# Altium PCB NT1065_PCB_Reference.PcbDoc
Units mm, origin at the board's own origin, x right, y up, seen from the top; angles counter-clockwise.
Board outline 27.75 x 27.4 mm, 4 copper layers (Top Layer, 02In, 03In, Bottom Layer), stack 1.418 mm thick; 37 components, 41 nets, 161 pads, 117 vias.
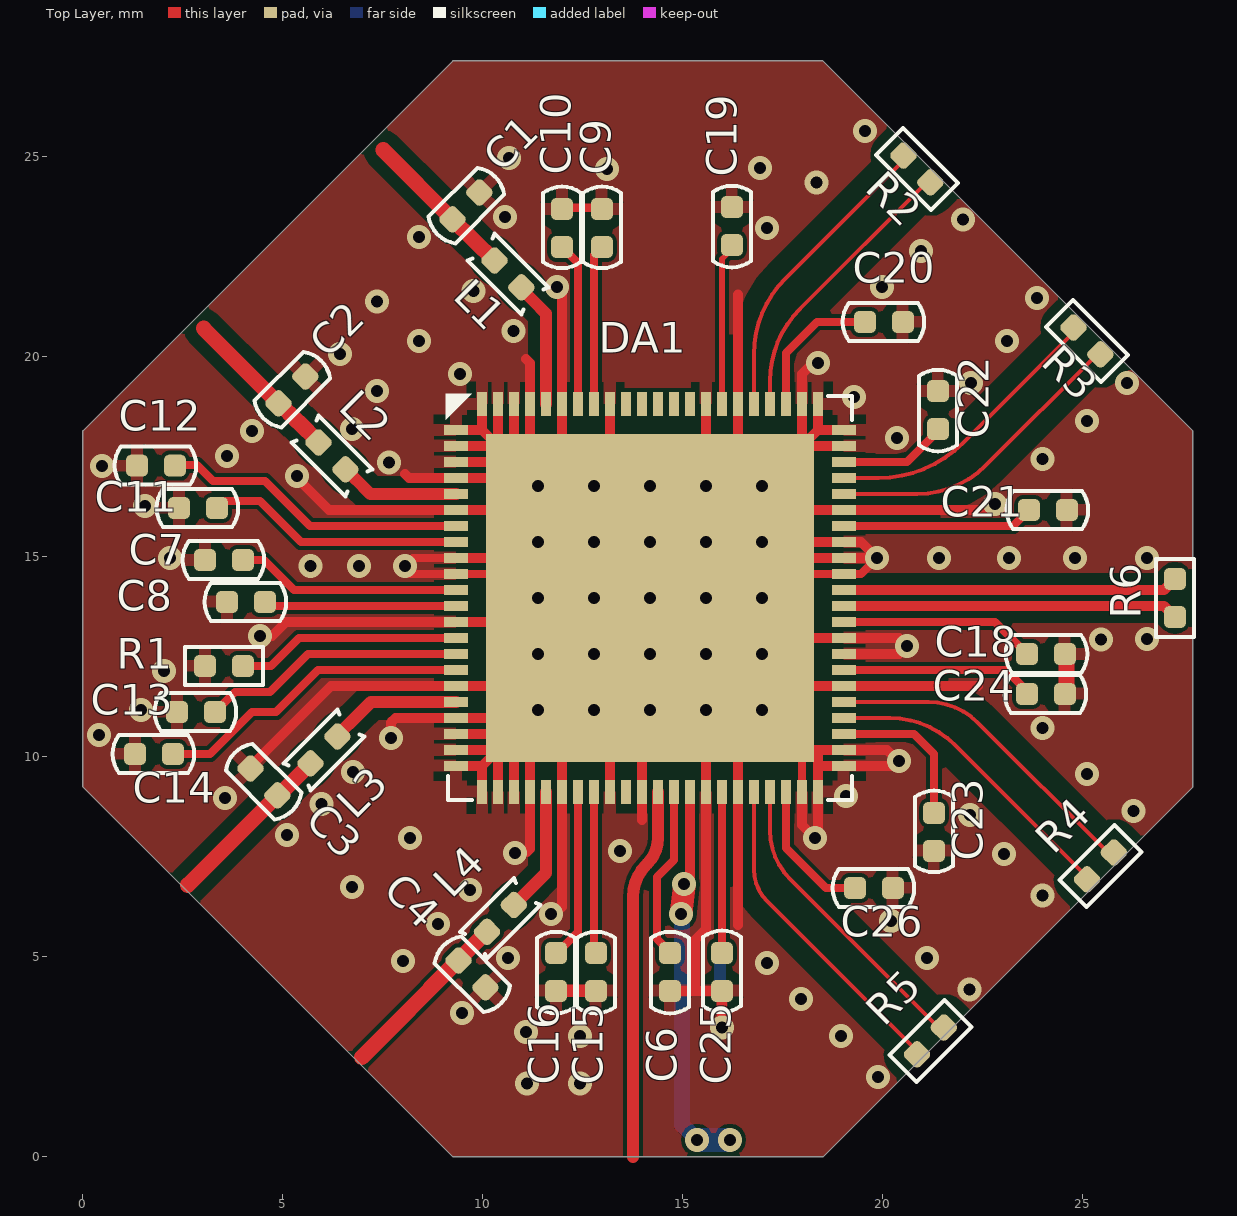
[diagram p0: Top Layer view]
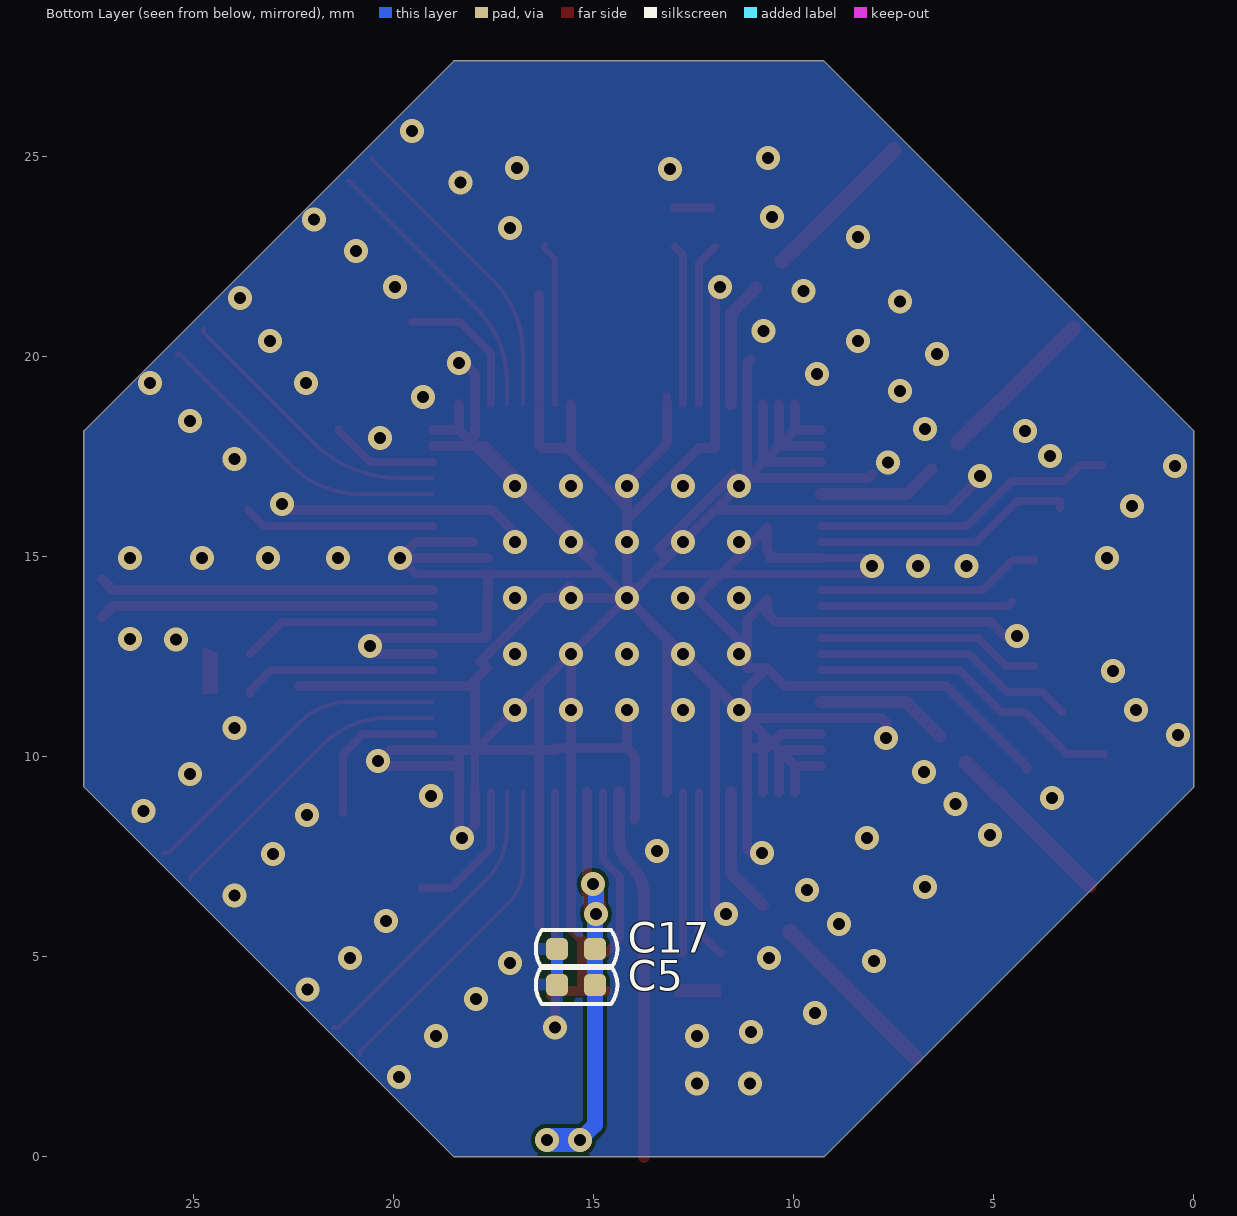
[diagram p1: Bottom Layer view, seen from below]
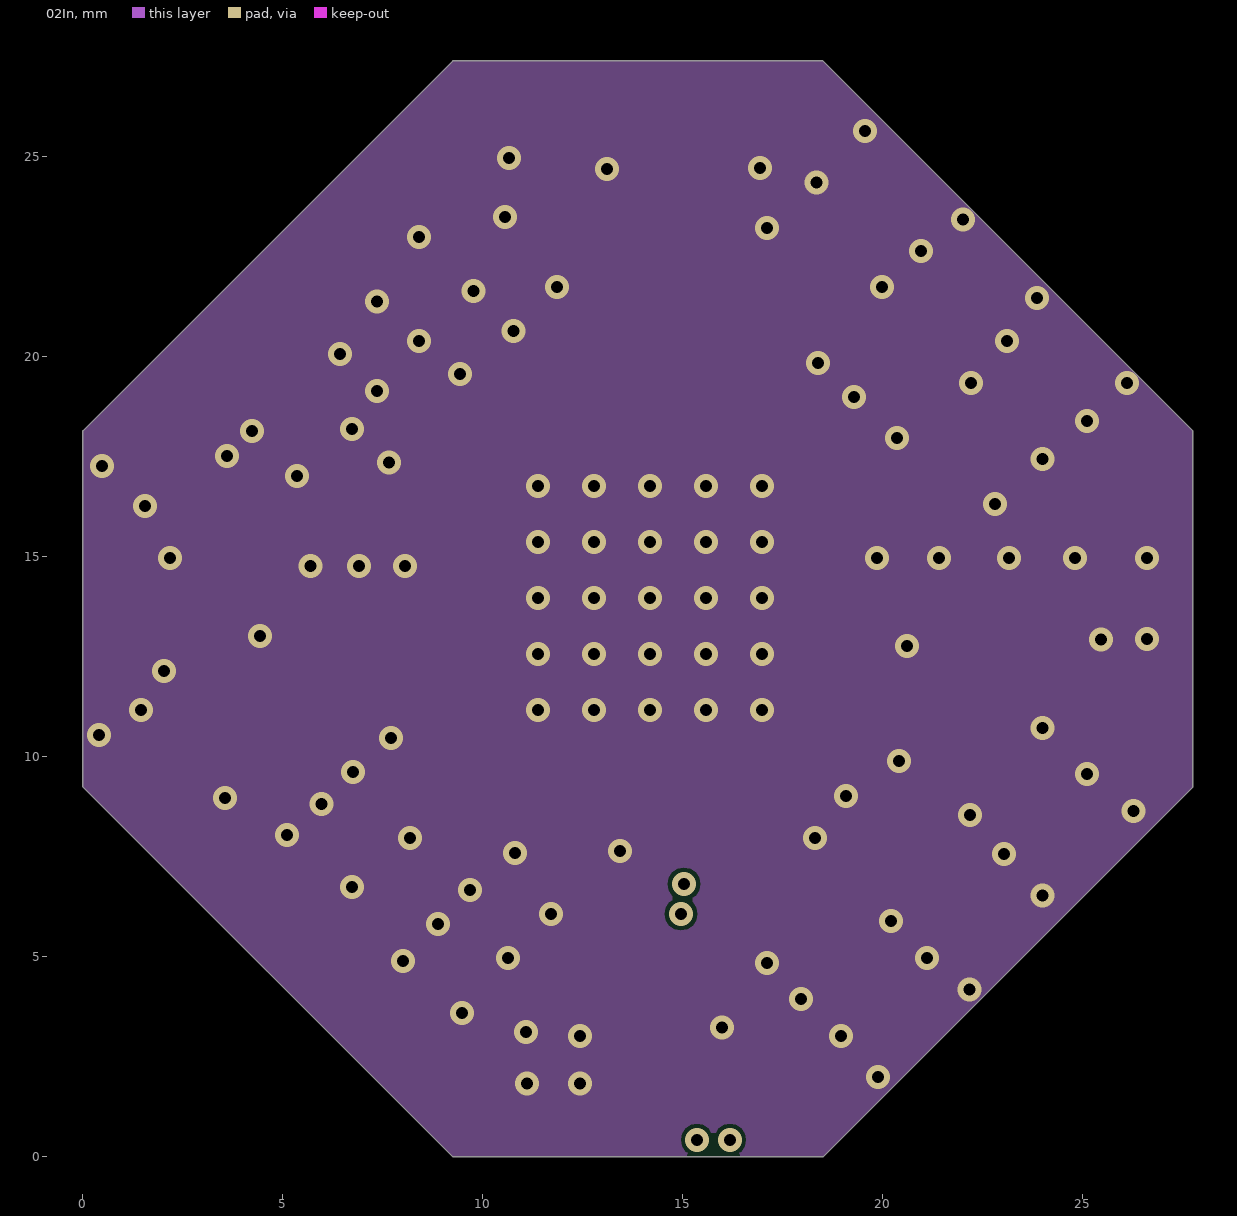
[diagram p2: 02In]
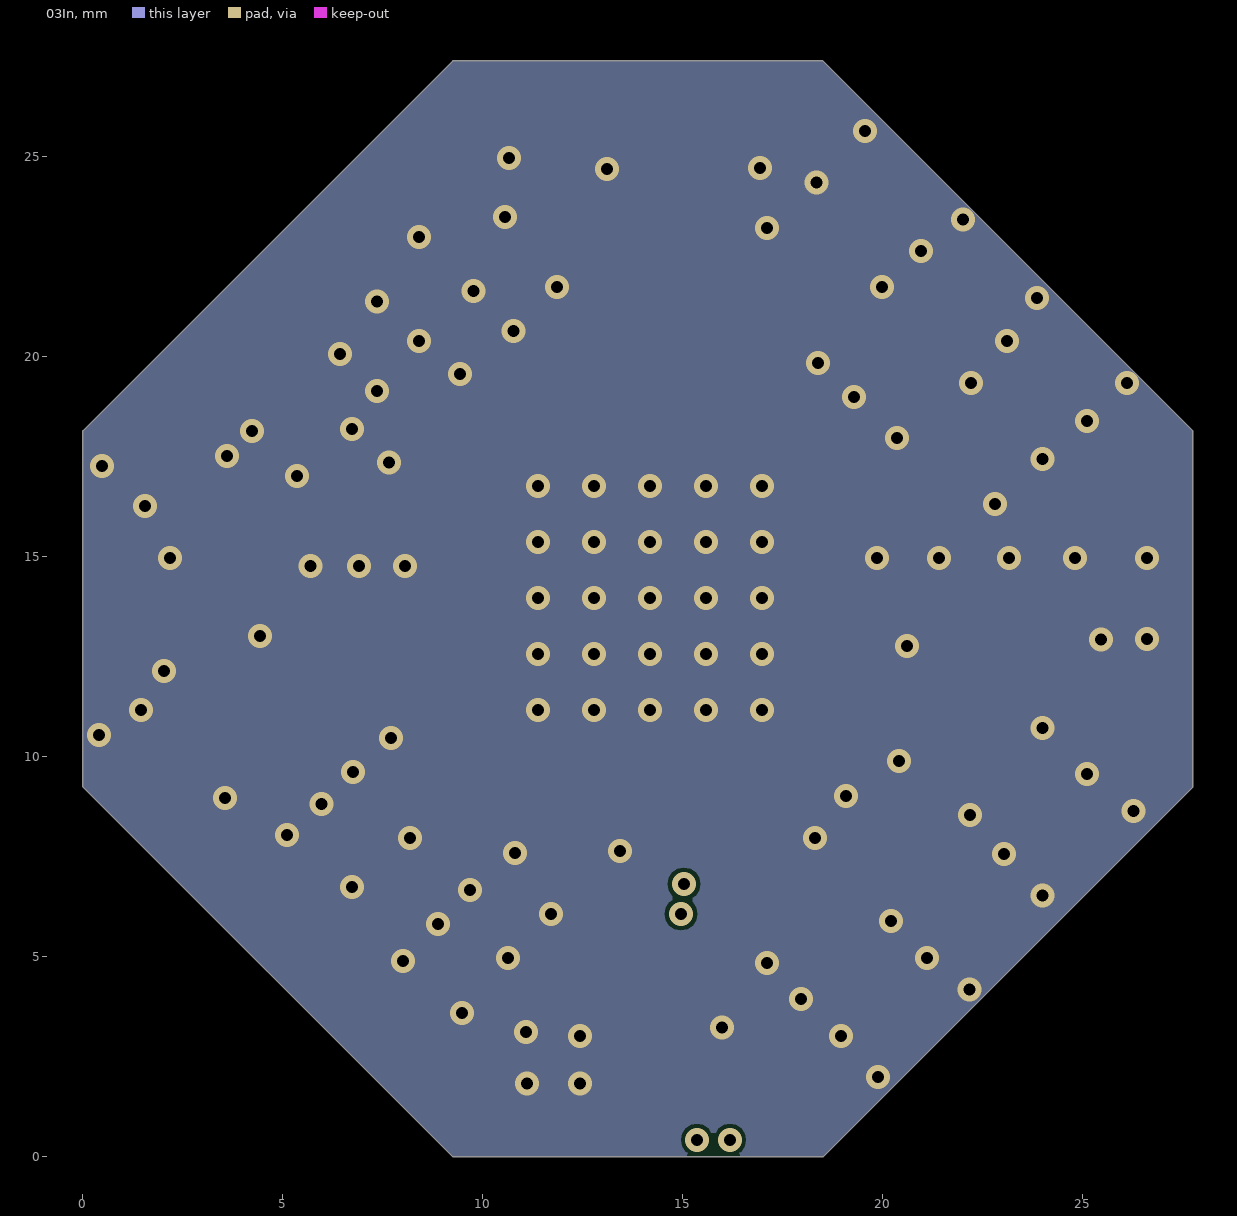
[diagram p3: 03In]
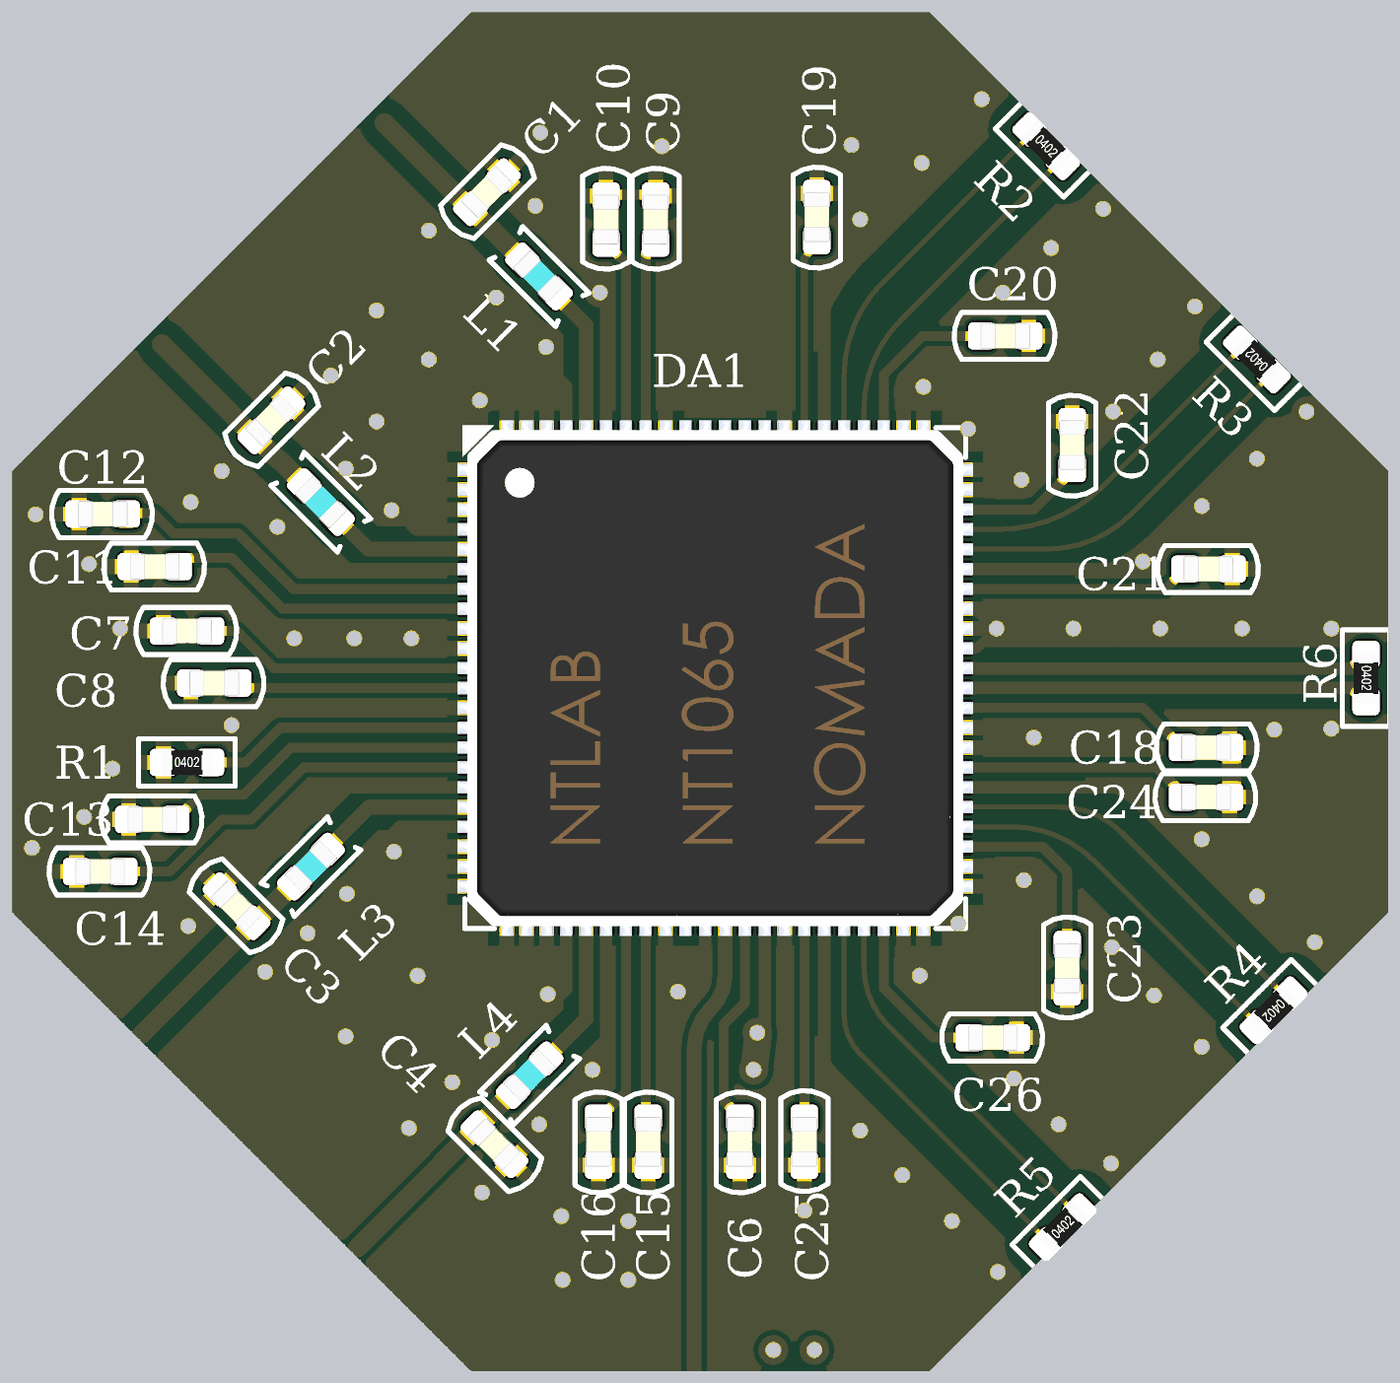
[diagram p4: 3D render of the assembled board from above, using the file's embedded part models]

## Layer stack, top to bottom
Top Solder: solder mask 0.025, Solder Resist, Dk 3.6
Top Layer: signal copper 0.053
RO4003C 0.203mm 18um/18um: core 0.203, RO4003C, Dk 3.55
02In: signal copper 0.018
PP7628-45 0.18mm: prepreg 0.18, PP7628-45, Dk 4.5
High Tg 0,51mm 35??m/35??m: core 0.51, High Tg 0,51mm, Dk 4.5
PP7628-45 0.18mm: prepreg 0.18, PP7628-45, Dk 4.5
03In: signal copper 0.018
RO4003C 0.203mm 18um/18um: core 0.203, RO4003C, Dk 3.55
Bottom Layer: signal copper 0.053
Bottom Solder: solder mask 0.025, Solder Resist, Dk 3.6

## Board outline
0,9.25 0,18.15 9.25,27.4 18.5,27.4 27.75,18.15 27.75,9.25 18.5,0 9.25,0

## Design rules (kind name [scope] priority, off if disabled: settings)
Clearance Clearance_poly_inner [inpoly  and onmid vs inpoly] p1: gap=0.25 ignorepadtopadclearanceinfootprint=FALSE
Clearance Clearance_poly-Diff100 [(IsTrack or IsArc) and InDifferentialPairClass('100Ohm_Diff') vs inpoly  and OnOutside] p2: gap=0.3 ignorepadtopadclearanceinfootprint=FALSE except(0: Arc-Hole Track-Hole SMDPad-Hole THPad-Hole Via-Hole Fill-Hole Poly-Hole Region-Hole Text-Hole)
Clearance Clearance_poly-50Ohm [(IsTrack or IsArc or ispad) and InNetClass('50Ohm') vs inpoly] p3: gap=0.3 ignorepadtopadclearanceinfootprint=FALSE
Clearance Clearance_poly-200Ohm [(IsTrack or IsArc or ispad) and InDifferentialPairClass('200Ohm_Diff') vs inpoly] p4: gap=0.5 ignorepadtopadclearanceinfootprint=FALSE
Clearance [All] p5: gap=0.1 ignorepadtopadclearanceinfootprint=FALSE
ComponentClearance [All] p1: gap=0.2 collisioncheckmode=3 verticalgap=0.15 showdistances=FALSE
DiffPairsRouting DiffPairsRouting_200Ohm [InDifferentialPairClass('200Ohm_Diff')] p1: maxlimit=0.7 minlimit=0.45 mostfreqgap=0.7 toplayer_minwidth=0.1 toplayer_maxwidth=0.1 toplayer_prefwidth=0.1 midlayer1_mingap=0 midlayer1_maxgap=0 midlayer1_prefgap=0 midlayer1_minwidth=0 midlayer1_maxwidth=0 midlayer1_prefwidth=0 midlayer4_mingap=0 midlayer4_maxgap=0 midlayer4_prefgap=0 midlayer4_minwidth=0 midlayer4_maxwidth=0 midlayer4_prefwidth=0 bottomlayer_minwidth=0.1 bottomlayer_maxwidth=0.1 bottomlayer_prefwidth=0.1 maxuncoupledlength=12.7
DiffPairsRouting DiffPairsRouting_100Ohm [InDifferentialPairClass('100Ohm_Diff')] p2: maxlimit=0.14 minlimit=0.14 mostfreqgap=0.14 toplayer_minwidth=0.25 toplayer_maxwidth=0.25 toplayer_prefwidth=0.25 midlayer1_mingap=0 midlayer1_maxgap=0 midlayer1_prefgap=0 midlayer1_minwidth=0 midlayer1_maxwidth=0 midlayer1_prefwidth=0 midlayer4_mingap=0 midlayer4_maxgap=0 midlayer4_prefgap=0 midlayer4_minwidth=0 midlayer4_maxwidth=0 midlayer4_prefwidth=0 bottomlayer_minwidth=0.25 bottomlayer_maxwidth=0.25 bottomlayer_prefwidth=0.25 maxuncoupledlength=12.7
HoleSize [All] p1: absolutevalues=TRUE maxlimit=5 minlimit=0.025 maxpercent=80.000 minpercent=20.000
HoleToHoleClearance [All] p1: gap=0.2 allowstackedmicrovias=TRUE
MinimumSolderMaskSliver [All] p1: minsoldermaskwidth=0.05
PolygonConnect PolygonConnect_Relief [IsNamedPolygon('GND_Top') or IsNamedPolygon('GND_Bot') vs ispad] p1: connectstyle=Relief reliefconductorwidth=0.3 reliefentries=4 polygonreliefangle="90 Angle" airgapwidth=0.25
PolygonConnect PolygonConnect_Direct [IsPoly vs ispad] p2: connectstyle=Direct reliefconductorwidth=0.254 reliefentries=4 polygonreliefangle="90 Angle" airgapwidth=0.254
PolygonConnect PolygonConnect_via [isvia] p3: connectstyle=Direct reliefconductorwidth=0.254 reliefentries=4 polygonreliefangle="90 Angle" airgapwidth=0.254
RoomDefinition NT1065_PCB_Reference_Sh1 [InComponentClass('NT1065_PCB_Reference_Sh1')] p1: confinementstyle=ConfineIn formatcopy=TRUE lockcomponents=FALSE outline 0.05,-0.05 27.75,-0.05 27.75,27.35 0.05,27.35
RoutingVias [All] p1: holewidth=0.3 width=0.6 viastyle="Through Hole" minholewidth=0.3 minwidth=0.6 maxholewidth=0.6 maxwidth=1.2
SilkToSilkClearance [All] p1: silktosilkclearance=0.1
SilkToSolderMaskClearance SilkToSolderMaskClearance_Pad [IsPad] p1: minsilkscreentomaskgap=0.099 clearancetoexposedcopper=TRUE
SolderMaskExpansion SolderMaskExpansion_via [isvia] p1: expansion=-125
SolderMaskExpansion [All] p2: expansion=0.075
Width Width_50Ohm [InNetClass('50Ohm')] p1: maxlimit=0.39 minlimit=0.3 preferedwidth=0.39 midlayer1_minwidth=0 midlayer1_maxwidth=0 midlayer1_prefwidth=0 midlayer4_minwidth=0 midlayer4_maxwidth=0 midlayer4_prefwidth=0 minimp=50.000000 maximp=50.000000 favimp=50.000000
Width [All] p2: maxlimit=1 minlimit=0.1 preferedwidth=0.3 midlayer1_minwidth=0.15 midlayer4_minwidth=0.15 bottomlayer_minwidth=0.15 minimp=50.000000 maximp=50.000000 favimp=50.000000
23 further rules are at their usual default settings.

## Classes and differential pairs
differential pair class 200Ohm_Diff: IF1_OUT IF2_OUT IF3_OUT IF4_OUT
differential pair class 100Ohm_Diff: CLK_OUT
net class 50Ohm: NetC1_1 NetC2_1 NetC3_1 NetDA1_5 NetDA1_18 NetDA1_27 NetDA1_84
differential pair IF4_OUT: +IF4_OUT_p -IF4_OUT_n
differential pair IF3_OUT: +IF3_OUT_p -IF3_OUT_n
differential pair IF2_OUT: +IF2_OUT_p -IF2_OUT_n
differential pair IF1_OUT: +IF1_OUT_p -IF1_OUT_n
differential pair CLK_OUT: +CLK_OUT_p -CLK_OUT_n

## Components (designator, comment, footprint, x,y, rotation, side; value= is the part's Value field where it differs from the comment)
C1 "1.2pF" 0402_C 9.575,23.775 r45 top value=1.2p
C2 "1.2pF" 0402_C 5.225,19.175 r45 top value=1.2p
C3 "1.2pF" 0402_C 4.525,9.375 r135 top value=1.2p
C4 "1.2pF" 0402_C 9.725,4.575 r315 top value=1.2p
C5 "100n" 0402_C 15.45,4.3 r180 bottom
C6 "1u" 0402_C 14.675,4.625 r270 top
C7 "1u" 0402_C 3.525,14.925 r180 top
C8 "1u" 0402_C 4.075,13.875 r180 top
C9 "1u" 0402_C 12.975,23.225 r90 top
C10 "1u" 0402_C 11.975,23.225 r90 top
C11 "1u" 0402_C 2.875,16.225 r180 top
C12 "1u" 0402_C 1.825,17.285 r180 top
C13 "1u" 0402_C 2.825,11.125 r180 top
C14 "1u" 0402_C 1.775,10.075 r180 top
C15 "1u" 0402_C 12.825,4.625 r270 top
C16 "1u" 0402_C 11.825,4.625 r270 top
C17 "1n" 0402_C 15.45,5.2 r180 bottom
C18 "1u" 0402_C 24.075,12.575 r0 top
C19 "1u" 0402_C 16.225,23.275 r270 top
C20 "1u" 0402_C 20.025,20.875 r180 top
C21 "1u" 0402_C 24.125,16.175 r180 top
C22 "1u" 0402_C 21.375,18.675 r270 top
C23 "1u" 0402_C 21.275,8.125 r90 top
C24 "1u" 0402_C 24.075,11.575 r180 top
C25 "1u" 0402_C 15.975,4.625 r90 top
C26 "1u" 0402_C 19.775,6.725 r180 top
DA1 "NT1068-QFN88" QFN-88_NT1065 14.175,13.975 r270 top
L1 "8.2nH" 0402_L 10.625,22.075 r135 top
L2 "8.2nH" 0402_L 6.225,17.525 r135 top
L3 "10nH" 0402_L 6.025,10.175 r225 top
L4 "10nH" 0402_L 10.435,5.965 r225 top
R1 "61.9k" 0402_R 3.525,12.275 r0 top
R2 "200" 0402_R 20.85,24.7 r315 top
R3 "200" 0402_R 25.1,20.4 r135 top
R4 "200" 0402_R 25.436,7.275 r225 top
R5 "200" 0402_R 21.186,2.9 r45 top
R6 "200" 0402_R 27.3,13.975 r270 top

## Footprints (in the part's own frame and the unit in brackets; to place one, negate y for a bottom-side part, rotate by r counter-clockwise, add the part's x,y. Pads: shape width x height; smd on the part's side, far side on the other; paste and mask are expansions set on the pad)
0402_C [mm]
  rrect50% 0.55x0.55 smd paste-0.05 mask+0.05: 1(-0.475,0) 2(0.475,0)
  silkscreen extent -1.01,-0.47 1.03,0.48, body extent -0.75,-0.27 0.75,0.27, height 0.36
0402_L [mm]
  rrect50% 0.55x0.55 smd paste-0.05 mask+0.05: 1(-0.475,0) 2(0.475,0)
  silkscreen extent -0.95,-0.47 0.95,0.47, body extent -0.75,-0.27 0.75,0.27, height 0.36
0402_R [mm]
  rrect50% 0.55x0.55 smd paste-0.05 mask+0.05: 1(-0.475,0) 2(0.475,0)
  silkscreen extent -0.97,-0.48 0.97,0.48, body extent -0.75,-0.27 0.75,0.27, height 0.35
QFN-88_NT1065 [mm] "Author : Golubev S.V."
  rect 0.25x0.6 smd mask+0.05: 1(-4.2,-4.85) 2(-3.8,-4.85) 3(-3.4,-4.85) 4(-3,-4.85) 5(-2.6,-4.85) 6(-2.2,-4.85) 7(-1.8,-4.85) 8(-1.4,-4.85) 9(-1,-4.85) 10(-0.6,-4.85) 11(-0.2,-4.85) 12(0.2,-4.85) 13(0.6,-4.85) 14(1,-4.85) 15(1.4,-4.85) 16(1.8,-4.85) 17(2.2,-4.85) 18(2.6,-4.85) 19(3,-4.85) 20(3.4,-4.85) 21(3.8,-4.85) 22(4.2,-4.85) 45(4.2,4.85) 46(3.8,4.85) 47(3.4,4.85) 48(3,4.85) 49(2.6,4.85) 50(2.2,4.85) 51(1.8,4.85) 52(1.4,4.85) 53(1,4.85) 54(0.6,4.85) 55(0.2,4.85) 56(-0.2,4.85) 57(-0.6,4.85) 58(-1,4.85) 59(-1.4,4.85) 60(-1.8,4.85) 61(-2.2,4.85) 62(-2.6,4.85) 63(-3,4.85) 64(-3.4,4.85) 65(-3.8,4.85) 66(-4.2,4.85)
  rect 0.6x0.25 smd mask+0.05: 23(4.85,-4.2) 24(4.85,-3.8) 25(4.85,-3.4) 26(4.85,-3) 27(4.85,-2.6) 28(4.85,-2.2) 29(4.85,-1.8) 30(4.85,-1.4) 31(4.85,-1) 32(4.85,-0.6) 33(4.85,-0.2) 34(4.85,0.2) 35(4.85,0.6) 36(4.85,1) 37(4.85,1.4) 38(4.85,1.8) 39(4.85,2.2) 40(4.85,2.6) 41(4.85,3) 42(4.85,3.4) 43(4.85,3.8) 44(4.85,4.2) 67(-4.85,4.2) 68(-4.85,3.8) 69(-4.85,3.4) 70(-4.85,3) 71(-4.85,2.6) 72(-4.85,2.2) 73(-4.85,1.8) 74(-4.85,1.4) 75(-4.85,1) 76(-4.85,0.6) 77(-4.85,0.2) 78(-4.85,-0.2) 79(-4.85,-0.6) 80(-4.85,-1) 81(-4.85,-1.4) 82(-4.85,-1.8) 83(-4.85,-2.2) 84(-4.85,-2.6) 85(-4.85,-3) 86(-4.85,-3.4) 87(-4.85,-3.8) 88(-4.85,-4.2)
  rect 8.2x8.2 smd paste-127 mask+0.05: 89(0,0)
  silkscreen extent -5.1,-5.1 5.05,5.05, body extent -5.2,-5.2 5.2,5.2, height 0.85

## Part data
C1 C2 C3 C4: library part "C 1.2", "1.2pF, +-0.25pF, 50V, 0402, COG"
C5: library part "C 104", "0.1uF, 10%, 16V, 0402, X7R"
C6 C7 C8 C9 C10 C11 C12 C13 C14 C15 C16 C18 C19 C20 C21 C22 C23 C24 C25 C26: library part "C 105", "1uF 10%, 10V, 0402, X5R"
C17: library part "C 102", "1nF, 5%, 25V, 0402, C0G"
DA1: library part "DA NT1065", "RF Front-End, ADC, QFN88"
L1 L2: library part L8.2_1, "8.2nH, 2%, 0.54A, 0402", Part Number=L3.6
L3 L4: library part L100, "10 nH, 2%, 0.54A, 0402", Part Number=L3.6
R1: library part "R 6192", "61.9 kOhm, 1%, 0402"
R2 R3 R4 R5 R6: library part R201, "200 Ohm, 5%, 0402"

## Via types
v1: diameter 0.6, hole 0.3, Top Layer to Bottom Layer, 64 vias
v2: diameter 0.6, hole 0.3, Top Layer to Bottom Layer, tented both sides, 53 vias

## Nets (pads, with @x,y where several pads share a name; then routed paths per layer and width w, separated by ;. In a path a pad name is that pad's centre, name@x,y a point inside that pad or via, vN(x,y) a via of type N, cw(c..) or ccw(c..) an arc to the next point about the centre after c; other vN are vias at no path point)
CLK_OUT_n: DA1.55 R6.2 | length 8.4
  Top Layer w0.25: DA1.55 19.45,13.775 19.455,13.78 25.82,13.78 27.02,13.78 R6.2
CLK_OUT_p: DA1.56 R6.1 | length 8.4
  Top Layer w0.25: DA1.56 19.45,14.175 19.455,14.17 25.82,14.17 27.02,14.17 R6.1
GND: C1.2 C2.2 C3.2 C4.2 C5.1 C6.2 C7.2 C8.2 C9.2 C10.2 C11.2 C12.2 C13.2 C14.2 C15.2 C16.2 C17.1 C18.2 C19.1 C20.1 C21.1 C22.1 C23.1 C24.1 C25.1 C26.1 DA1.1 DA1.2 DA1.3 DA1.4 DA1.6 DA1.9 DA1.10 DA1.13 DA1.17 DA1.19 DA1.20 DA1.21 DA1.22 DA1.23 DA1.24 DA1.25 DA1.26 DA1.28 DA1.31 DA1.33 DA1.37 DA1.39 DA1.43 DA1.44 DA1.45 DA1.46 DA1.50 DA1.52 DA1.53 DA1.57 DA1.58 DA1.59 DA1.61 DA1.65 DA1.66 DA1.67 DA1.68 DA1.72 DA1.74 DA1.80 DA1.83 DA1.85 DA1.86 DA1.87 DA1.88 DA1.89 R1.1 | length 201.6
  Top Layer w0.2: v2@8.05,14.975 v2(8.05,14.775) ; DA1.9 8.25,14.975 v2(8.05,14.775) ; DA1.3 DA1.3@9.355,17.375 ; DA1.89@13.175,14.975 DA1.89@13.575,14.575 ; DA1.80 DA1.80@13.175,19.025 ; DA1.89@15.175,14.975 DA1.89@14.775,14.575 ; DA1.72 DA1.72@16.375,18.975 ; DA1.43 17.975,10.175 16.374,11.777 v2(15.575,12.575) v2(14.175,13.975) ; 19.425,14.975 19.45,14.975 ; v2(19.85,14.975) 19.45,14.575 DA1.57 17.65,14.575 DA1.89@14.775,14.575 ; v2(8.05,14.775) 8.05,14.575 DA1.10 11.825,14.575 DA1.89@13.575,14.575 ; DA1.89@13.575,14.575 13.925,14.225 v2(14.175,13.975) ; v2(14.175,13.975) DA1.89@14.775,14.575
  Top Layer w0.25: C3.2 4.189,9.764 6.2,11.775 DA1.17 10.225,11.775 DA1.89@10.675,12.225 ; v2(4.425,13.025) 4.725,13.025 5.075,13.375 10.45,13.375 10.675,13.6 10.675,13.925 11.175,13.425 DA1.89@11.175,12.725 ; v1(5.35,17.025) 5.35,16.975 6.15,16.175 DA1.6@9.345,16.175 ; v1(7.7,10.475) 7.7,10.866 7.81,10.975 DA1.19@9.395,10.975 ; 8.05,17.075 8.15,16.975 DA1.4 DA1.89@11.175,16.975 ; DA1.22 9.975,9.775 ; DA1.21 DA1.89@10.375,10.175 ; DA1.20 10.325,10.575 DA1.89@10.55,10.35 ; DA1.19 DA1.89@11.175,10.975 ; DA1.9 10.6,14.975 10.6,15.075 10.675,15.15 10.675,15.725 11.825,14.575 12.425,13.975 DA1.89@11.175,12.725 ; DA1.6 DA1.89@11.975,16.175 ; DA1.3 DA1.89@10.775,17.375 ; DA1.2 DA1.89@10.375,17.775 ; DA1.1 9.975,18.175 ; DA1.23 9.975,9.775 ; DA1.88 9.975,18.175 ; DA1.24 DA1.89@10.375,10.175 ; DA1.87 DA1.89@10.375,17.775 ; DA1.25 DA1.89@10.775,10.225 ; DA1.86 DA1.89@10.775,17.375 ; 11.075,19.95 11.175,19.85 DA1.85 DA1.89@11.175,16.975 ; 11.1,7.625 11.175,7.7 DA1.26 DA1.89@11.175,10.225 ; v2(11.85,21.75) 11.875,21.75 11.975,21.65 DA1.83 11.975,17.725 12.375,17.725 DA1.89@14.175,15.925 ; 11.975,6.245 11.975,6.25 11.975,6.915 ; DA1.31 DA1.89@13.175,12.925 ; DA1.80 13.175,17.825 14.175,16.825 v2(14.175,16.775) DA1.89@14.175,16.225 ; v2@13.3,7.575 v2@13.425,7.575 ; DA1.89@13.925,14.225 DA1.89@14.125,14.225 ; 13.975,8.426 DA1.33 13.975,10.025 DA1.89@14.175,10.225 ; DA1.89@14.175,10.975 DA1.89@14.175,10.225 ; C6.2 15.3,4.15 ; v2(15.575,12.575) v2(15.575,11.175) DA1.89@15.575,10.225 ; v2(15.575,13.975) v2(14.175,13.975) ; DA1.74 DA1.89@15.575,17.625 ; DA1.89@15.638,14.263 15.925,13.975 16.25,13.975 17.838,12.388 17.675,12.225 DA1.89@17.975,11.925 ; v1(15.975,3.236) C25.1@15.975,4.075 ; C25.1@16.075,4.025 16.025,4.025 C25.1@15.975,4.075 ; DA1.89@16.374,11.777 DA1.89@16.374,10.175 ; 16.375,5.8 DA1.39 16.375,10.173 DA1.89@16.374,10.175 ; DA1.72 16.375,17.8 16.3,17.725 15.675,17.725 DA1.89@15.575,17.625 ; DA1.72@16.375,18.975 16.375,21.559 ; DA1.89@16.863,15.488 17.55,16.175 v2@22.575,16.175 ; v1(17.1,4.85) 17.125,4.85 v1@17.125,4.925 ; v1(17.1,23.225) v1@17.125,23.225 ; DA1.89@17.65,14.575 17.65,13.95 17.675,13.925 17.675,13.025 17.725,12.975 DA1.53 v1@20.4,12.975 ; DA1.89@17.65,14.975 19.425,14.975 ; DA1.43 17.975,8.3 v2(18.3,7.975) 18.375,8.05 DA1.44 18.375,9.8 ; DA1.89@18.025,15.375 DA1.59 19.45,15.375 v2(19.85,14.975) 19.45,14.975 ; DA1.67 18.375,18.175 ; v1(18.375,19.85) v1@18.375,19.975 ; v1@18.5,19.975 v1@18.375,19.975 ; DA1.52 20.4,12.575 v1(20.6,12.775) ; DA1.65 DA1.89@17.975,17.775 ; DA1.66 18.375,18.175 ; v1@20.375,9.775 DA1.45 18.4,9.775 18.375,9.8 ; v1(20.4,9.9) 20.375,9.9 20.1,10.175 DA1.46 18.341,10.175 ; 22.371,11.775 DA1.50 18.125,11.775 DA1.89@17.975,11.925 ; v1(25.1,18.4) v1@25.15,18.4 ; 9.975,9.775 DA1.89@10.375,10.175 ; 9.975,18.175 DA1.89@10.375,17.775 ; DA1.89@10.375,10.175 DA1.89@10.55,10.35 ; DA1.89@10.375,17.775 DA1.89@10.775,17.375 ; DA1.89@10.55,10.35 DA1.89@10.775,10.575 ; DA1.89@10.55,10.35 10.675,10.225 DA1.89@10.775,10.225 ; DA1.89@10.675,12.225 11.175,12.225 DA1.89@11.175,12.725 ; DA1.89@10.675,12.225 11.175,11.725 DA1.89@11.175,10.975 ; DA1.89@10.775,10.225 DA1.89@11.175,10.225 ; DA1.89@10.775,10.225 DA1.89@10.775,10.575 ; DA1.89@10.775,10.575 DA1.89@11.175,10.975 ; DA1.89@10.775,17.375 DA1.89@11.175,16.975 ; DA1.89@11.175,10.225 DA1.89@11.175,10.925 ; DA1.89@11.175,10.925 DA1.89@11.975,11.725 ; DA1.89@11.175,10.925 DA1.89@11.175,10.975 ; DA1.89@11.175,10.975 v2(11.375,11.175) DA1.89@11.975,11.775 ; DA1.89@11.175,16.975 DA1.89@11.3,16.85 ; DA1.89@11.3,16.85 11.513,17.063 13.388,15.188 13.175,14.975 DA1.89@11.975,16.175 ; DA1.89@11.3,16.85 v2(11.375,16.775) DA1.89@11.975,16.175 ; 11.975,6.915 11.975,6.935 ; 11.975,6.915 11.975,6.925 11.975,6.935 ; 11.975,6.935 DA1.28 DA1.89@11.975,11.725 ; DA1.89@11.975,11.725 DA1.89@13.175,12.925 ; DA1.89@11.975,11.725 DA1.89@11.975,11.775 ; DA1.89@11.975,11.775 v2(12.775,12.575) DA1.89@13.175,12.975 ; DA1.89@13.175,12.925 13.6,13.35 13.575,13.375 v2(14.175,13.975) ; DA1.89@13.175,12.925 DA1.89@13.175,12.975 ; DA1.89@13.175,12.975 v2(14.175,13.975) ; DA1.89@14.175,10.225 DA1.89@15.575,10.225 ; v2(14.175,13.975) v2(14.175,15.375) DA1.89@14.175,15.925 ; DA1.89@14.175,15.925 DA1.89@14.175,16.225 ; DA1.89@14.175,16.225 DA1.89@15.575,17.625 ; 15.3,4.15 15.3,5.425 15.575,5.7 DA1.37 DA1.89@15.575,10.225 ; 15.3,4.15 C25.1 C25.1@15.975,4.075 ; DA1.89@15.575,10.225 15.95,10.225 15.95,10.175 DA1.89@16.374,10.175 ; DA1.89@16.374,10.175 DA1.89@17.975,10.175 ; DA1.89@17.975,10.175 18.341,10.175 ; DA1.89@17.975,10.175 DA1.89@17.975,11.925 ; DA1.89@17.975,17.775 DA1.89@18.113,17.913 ; DA1.89@17.975,17.775 v2(16.975,16.775) v2(15.575,15.375) 15.175,14.975 15.05,15.1 17.725,17.775 DA1.89@17.975,17.775 ; DA1.89@18.113,17.913 17.975,18.05 DA1.68 17.975,19.575 v1@18.375,19.975 ; DA1.89@18.113,17.913 18.375,18.175 ; 18.341,10.175 18.375,10.141 18.375,9.8
  Bottom Layer w0.3: C5.1 C17.1
  other v1: 12.425,1.838 19.875,2 12.425,3.025 18.95,3.025 11.075,3.125 9.475,3.6 17.95,3.95 8,4.9 10.625,4.975 21.1,4.975 8.875,5.825 20.2,5.9 11.7,6.075 23.987,6.541 9.675,6.675 23.025,7.575 10.8,7.6 5.1,8.05 22.175,8.55 26.266,8.65 3.55,8.975 19.075,9.025 25.103,9.572 6.75,9.625 0.4,10.55 1.45,11.175 2.025,12.15 2.175,14.975 1.55,16.275 0.475,17.275 7.65,17.36 3.6,17.525 20.35,17.975 4.225,18.15 6.725,18.2 19.275,19 22.2,19.35 9.43,19.575 6.425,20.075 8.4,20.4 23.1,20.4 10.767,20.65 23.85,21.47 9.76,21.65 19.975,21.75 20.95,22.65 8.4,23 10.55,23.5 18.341,24.364 13.1,24.7 16.925,24.725 10.65,24.975 19.55,25.65
  other v2: 11.1,1.838 22.157,4.188 6.725,6.748 13.425,7.65 8.175,7.975 5.96,8.83 23.987,10.725 12.775,11.175 14.175,11.175 16.975,11.175 11.375,12.575 14.175,12.575 16.975,12.575 25.45,12.936 26.6,12.955 11.375,13.975 12.775,13.975 16.975,13.975 5.689,14.775 6.9,14.775 21.4,14.975 23.15,14.975 24.8,14.975 26.6,14.975 11.375,15.375 12.775,15.375 16.975,15.375 22.8,16.325 12.775,16.775 15.575,16.775 23.99,17.444 7.35,19.15 26.1,19.35 7.35,21.389 22,23.439
IF1_OUT_n: DA1.70 R2.2 | length 7.1
  Top Layer w0.1: DA1.70 17.175,19.398 cw(c19.715,19.398) 17.919,21.194 R2.2@21.138,24.412
IF1_OUT_p: DA1.71 R2.1 | length 7.6
  Top Layer w0.1: DA1.71 16.775,20.072 cw(c19.453,20.072) 17.56,21.966 R2.1@20.572,24.978
IF2_OUT_n: DA1.63 R3.2 | length 7.2
  Top Layer w0.1: DA1.63 19.888,16.975 ccw(c19.888,19.962) 22,17.85 24.764,20.614 R3.2
IF2_OUT_p: DA1.62 R3.1 | length 7.8
  Top Layer w0.1: DA1.62 20.853,16.575 ccw(c20.853,18.997) 22.566,17.284 25.345,20.064 R3.1
IF3_OUT_n: DA1.48 R4.2 | length 7.7
  Top Layer w0.1: DA1.48 20.17,10.975 cw(c20.17,8.67) 21.8,10.3 25.1,7 R4.2
IF3_OUT_p: DA1.49 R4.1 | length 8.2
  Top Layer w0.1: DA1.49 21.136,11.375 cw(c21.136,9.636) 22.366,10.866 25.621,7.611 R4.1
IF4_OUT_n: DA1.41 R5.2 | length 7.7
  Top Layer w0.1: DA1.41 17.175,8.157 ccw(c18.882,8.157) 17.675,6.95 21.389,3.236 R5.2
IF4_OUT_p: DA1.40 R5.1 | length 8.2
  Top Layer w0.1: DA1.40 16.775,7.191 ccw(c17.917,7.191) 17.11,6.384 20.85,2.644 R5.1
NetC1_1: C1.1 L1.2 | length 3.9
  Top Layer w0.39: 7.505,25.174 C1.1 L1.2
NetC2_1: C2.1 L2.2 | length 4.1
  Top Layer w0.39: 3.015,20.714 C2.1 4.9,18.85 5.369,18.381 5.381,18.381 5.889,17.873 L2.2
NetC3_1: C3.1 L3.2 | length 4.3
  Top Layer w0.39: 2.622,6.8 C3.1 4.861,9.05 4.9,9.05 L3.2
NetC4_1: C4.1 L4.2 | length 5.4
  Top Layer w0.39: 6.968,2.489 C4.1 ; 8.671,4.211 10.085,5.625 L4.2@10.1,5.625 ; L4.2 L4.2@10.102,5.627
NetC5_2: C5.2 C17.2 DA1.36 | length 9.9
  Top Layer w0.25: v1(15.025,6.825) 15.025,6.775 15.175,6.925 DA1.36
  Bottom Layer w0.4: v1(14.95,6.075) v1@14.95,6.1 ; v1(15.025,6.825) 14.95,6.75 v1@14.95,6.1 ; v2(15.35,0.425) 14.975,0.8 C5.2 C17.2 14.975,6.075 v1@14.95,6.1
  Bottom Layer w0.6: v2(15.35,0.425) v2(16.175,0.425)
NetC6_1: C6.1 DA1.35 | length 4.3
  Top Layer w0.2: C6.1 14.675,5.125 14.35,5.45 14.35,7 14.775,7.425 DA1.35
NetC7_1: C7.1 DA1.11 | length 5.6
  Top Layer w0.2: C7.1 4.525,14.925 5.275,14.175 DA1.11
NetC8_1: C8.1 DA1.12 | length 4.8
  Top Layer w0.2: C8.1 4.65,13.775 DA1.12
NetC9_1: C9.1 DA1.81 | length 4
  Top Layer w0.2: DA1.81 12.775,22.55 C9.1
NetC10_1: C10.1 DA1.82 | length 4.1
  Top Layer w0.2: C10.1 12.375,22.35 DA1.82
NetC11_1: C11.1 DA1.8 | length 6.6
  Top Layer w0.2: C11.1 3.35,16.4 4.425,16.4 5.45,15.375 DA1.8
NetC12_1: C12.1 DA1.7 | length 7.7
  Top Layer w0.2: C12.1 2.3,17.3 2.85,17.3 3.25,16.9 4.55,16.9 5.675,15.775 DA1.7
NetC13_1: C13.1 DA1.15 | length 6.6
  Top Layer w0.2: C13.1 3.8,11.625 4.675,11.625 5.625,12.575 DA1.15
NetC14_1: C14.1 DA1.16 | length 7.9
  Top Layer w0.2: C14.1 3.175,10.075 4.225,11.125 4.825,11.125 5.875,12.175 DA1.16
NetC15_1: C15.1 DA1.30 | length 4.1
  Top Layer w0.2: DA1.30 12.775,5.1 C15.1
NetC16_1: C16.1 DA1.29 | length 4.3
  Top Layer w0.2: C16.1 11.85,5.1 12.375,5.625 DA1.29
NetC18_1: C18.1 DA1.54 | length 4.9
  Top Layer w0.2: DA1.54 22.8,13.375 23.575,12.6 23.6,12.6 C18.1
NetC19_2: C19.2 DA1.73 | length 4.1
  Top Layer w0.15: DA1.73 15.975,22.45 16.25,22.725 16.25,22.775 C19.2
NetC20_2: C20.2 DA1.69 | length 3.6
  Top Layer w0.2: DA1.69 17.575,20.1 18.275,20.8 18.35,20.875 C20.2
NetC21_2: C21.2 DA1.60 | length 4.8
  Top Layer w0.2: DA1.60 23.25,15.775 C21.2
NetC22_2: C22.2 DA1.64 | length 2.7
  Top Layer w0.2: DA1.64 20.6,17.375 21.375,18.15 C22.2
NetC23_2: C23.2 DA1.47 | length 3.9
  Top Layer w0.2: DA1.47 20.775,10.575 20.95,10.4 21.275,10.075 C23.2
NetC24_2: C24.2 DA1.51 | length 4.9
  Top Layer w0.2: DA1.51 23.075,12.175 23.6,11.65 C24.2
NetC25_2: C25.2 DA1.38 | length 4
  Top Layer w0.2: C25.2 DA1.38
NetC26_2: C26.2 DA1.42 | length 3.5
  Top Layer w0.2: DA1.42 17.575,7.725 17.875,7.425 18.575,6.725 C26.2
NetDA1_5: DA1.5 L2.1 | length 3
  Top Layer w0.3: L2.1 6.571,17.189 6.807,16.954 7.185,16.575 DA1.5
NetDA1_14: DA1.14 R1.2 | length 5.6
  Top Layer w0.2: R1.2 4.7,12.275 5.4,12.975 DA1.14
NetDA1_18: DA1.18 L3.1 | length 3.3
  Top Layer w0.3: L3.1 6.361,10.536 6.9,11.075 7.2,11.375 DA1.18
NetDA1_27: DA1.27 L4.1 | length 3.2
  Top Layer w0.3: L4.1@10.772,6.3 10.775,6.3 11.25,6.775 11.575,7.1 DA1.27
NetDA1_84: DA1.84 L1.1 | length 3.2
  Top Layer w0.3: L1.1 10.961,21.699 11.271,21.389 11.575,21.085 11.575,19.225 DA1.84
pads on no net: DA1.32 DA1.34 DA1.75 DA1.76 DA1.77 DA1.78 DA1.79
copper on no net: | length 9.3
  Top Layer w0.3: 13.75,0 13.75,6.5 cw(c14.896,6.5) 14.086,7.31 14.1,7.324 14.114,7.339 ccw(c13.483,7.969) 14.375,7.969 14.375,9.125

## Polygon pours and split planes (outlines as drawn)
GND on Top Layer "GND_Top" (solid, remove dead copper, pour order 80): 9.25,27.4 0,18.15 0,9.245 9.245,0 18.5,0 27.75,9.25 27.75,18.15 18.5,27.4
GND on 02In "GND_Top" (solid, remove dead copper, pour order 82): 9.25,27.4 0,18.15 0,9.245 9.245,0 18.5,0 27.75,9.25 27.75,18.15 18.5,27.4
GND on 03In "GND_Top" (solid, remove dead copper, pour order 84): 9.25,27.4 0,18.15 0,9.245 9.245,0 18.5,0 27.75,9.25 27.75,18.15 18.5,27.4
GND on Bottom Layer "GND_Bot" (solid, remove dead copper, pour order 86): 9.25,27.4 0,18.15 0,9.245 9.245,0 18.5,0 27.75,9.25 27.75,18.15 18.5,27.4

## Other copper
Top Layer:
  region net NetC5_2: 15.325,6.825 15.225,5.975 14.675,6.075 14.775,6.875
  region net GND: 11.985,23.825 11.985,23.625 13.085,23.625 13.085,23.825
  region net GND: 11.825,4.3 12.985,4.3 12.985,4 11.825,4 11.825,4.15
  region net GND: 24.4,12.591 24.4,11.575 24.785,11.575 24.785,12.725 24.7,12.725

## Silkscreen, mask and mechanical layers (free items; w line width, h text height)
Board:
  the board outline again, w0.01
